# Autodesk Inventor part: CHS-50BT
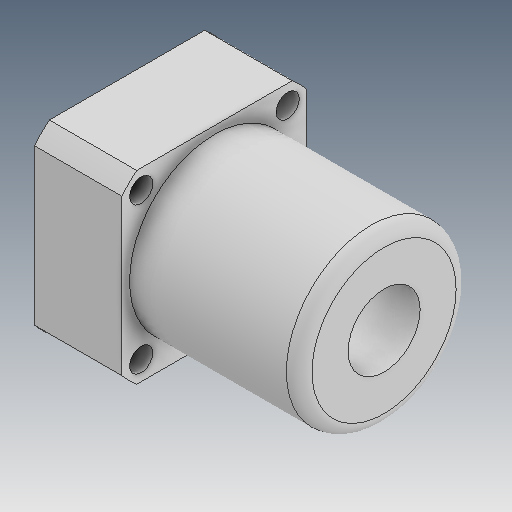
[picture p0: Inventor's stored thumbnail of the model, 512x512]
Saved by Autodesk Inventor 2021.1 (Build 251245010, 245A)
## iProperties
Created: 2019-04
Part Number: CHS-50BT
Material: Ogólny
Document SubType Name: Modeling
Designer: user
Density: 1 g/cm^3
Appearance: Domyślna
Author: user
Revision Number: ÈÎºÎ
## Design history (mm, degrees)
feature "ÊäÈë1"
node "Bryła1"
